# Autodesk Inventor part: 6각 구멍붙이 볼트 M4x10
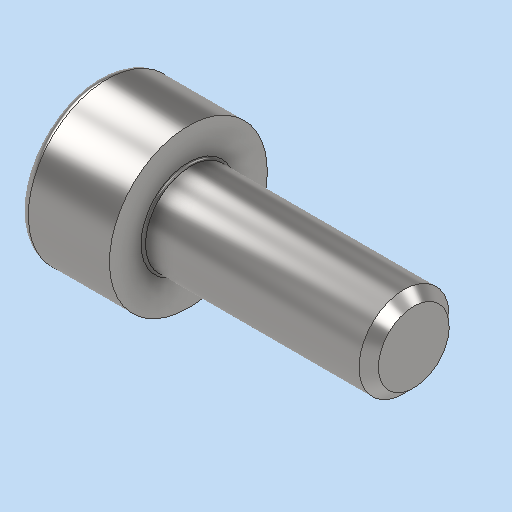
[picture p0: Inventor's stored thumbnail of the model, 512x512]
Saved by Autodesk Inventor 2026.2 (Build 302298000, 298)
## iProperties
Created: 2026-01
Part Number: 6각 구멍붙이 볼트 M4x10
Material: 강철, 연강
Description: 6각머리 태핑 나사
Document SubType Name: Modeling
Designer: PC2-07
Density: 7.85 g/cm^3
Appearance: 기본값
Author: jhkim
Sending System: Autodesk Inventor 2026
Preprocessor: ST-DEVELOPER v20.1
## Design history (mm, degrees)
feature "Solid1"
node "솔리드1"
